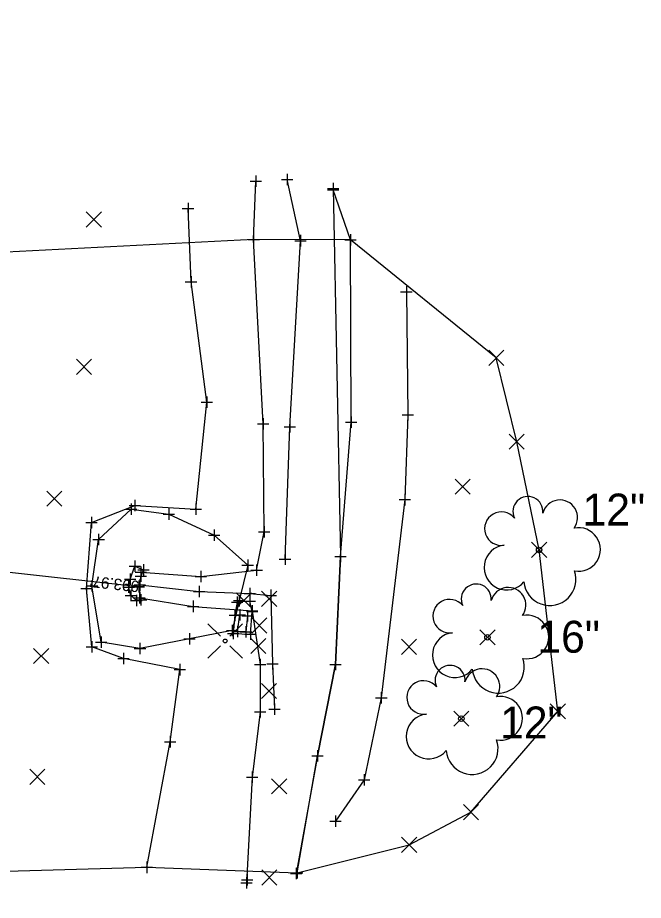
# Model space of a CAD drawing. Extents: x 160138 to 160780, y 488720 to 491073.
# Drawn here: x 160725.5 to 160780.4, y 489676.8 to 489754.3 of the extents above; entities that cross this region are included whole.
import ezdxf

# ---------------------------------------------------------------- set-up
doc = ezdxf.new("R2010")
doc.units = 0
for name, color, linetype in [('_CIVIL_CONSTRUCTION', 7, 'Continuous'), ('DR_X_Storm_Sewer', 7, 'Continuous'), ('RS_Raster1', 7, 'Continuous'), ('RW_X_CL_100_Bearings', 7, 'Continuous'), ('RW_X_CL_100_Cardinal_Points', 7, 'Continuous'), ('RW_X_CL_100_Curve_Data', 7, 'Continuous'), ('RW_X_CL_100_Stations', 7, 'Continuous'), ('SC_Scratch1', 7, 'Continuous'), ('SV_P_Control_Cells_Set', 7, 'Continuous'), ('SV_P_Mon_Cells_Set', 7, 'Continuous'), ('SV_X_Mon_Cells_Found', 7, 'Continuous'), ('SV_X_Random_Point', 7, 'Continuous'), ('SV_X_Terrain_Boundary', 7, 'Continuous'), ('VG_X_Text', 7, 'Continuous')]:
    doc.layers.add(name, color=color, linetype=linetype)

msp = doc.modelspace()

# ---------------------------------------------------------------- linework, layer by layer
at = {"layer": '_CIVIL_CONSTRUCTION'}
for p, q in [((160731.514, 489735.875), (160732.848, 489737.21)), ((160731.514, 489737.21), (160732.848, 489735.875)), ((160766.827, 489723.729), (160768.16, 489725.064)), ((160766.827, 489725.064), (160768.16, 489723.729)), ((160730.645, 489722.942), (160731.979, 489724.277)), ((160730.645, 489724.277), (160731.979, 489722.942)), ((160768.615, 489716.365), (160769.948, 489717.7)), ((160768.615, 489717.7), (160769.948, 489716.365)), ((160763.87, 489712.423), (160765.204, 489713.758)), ((160763.87, 489713.758), (160765.204, 489712.423)), ((160728.045, 489711.364), (160729.378, 489712.699)), ((160728.045, 489712.699), (160729.378, 489711.364)), ((160770.582, 489706.871), (160771.916, 489708.206)), ((160770.582, 489708.206), (160771.916, 489706.871)), ((160744.665, 489702.444), (160745.998, 489703.779)), ((160744.665, 489703.779), (160745.998, 489702.444)), ((160746.903, 489702.581), (160748.236, 489703.916)), ((160746.903, 489703.916), (160748.236, 489702.581)), ((160746.032, 489700.223), (160747.366, 489701.558)), ((160746.032, 489701.558), (160747.366, 489700.223)), ((160766.051, 489699.188), (160767.384, 489700.523)), ((160766.051, 489700.523), (160767.384, 489699.188)), ((160745.938, 489698.431), (160747.272, 489699.766)), ((160745.938, 489699.766), (160747.272, 489698.431)), ((160759.163, 489698.362), (160760.496, 489699.697)), ((160759.163, 489699.697), (160760.496, 489698.362)), ((160726.893, 489697.554), (160728.226, 489698.889)), ((160726.893, 489698.889), (160728.226, 489697.554)), ((160746.877, 489694.485), (160748.21, 489695.82)), ((160746.877, 489695.82), (160748.21, 489694.485)), ((160772.231, 489692.695), (160773.564, 489694.03)), ((160772.231, 489694.03), (160773.564, 489692.695)), ((160763.753, 489692.048), (160765.086, 489693.383)), ((160763.753, 489693.383), (160765.086, 489692.048)), ((160726.553, 489686.954), (160727.886, 489688.289)), ((160726.553, 489688.289), (160727.886, 489686.954)), ((160747.776, 489686.114), (160749.109, 489687.449)), ((160747.776, 489687.449), (160749.109, 489686.114)), ((160764.601, 489683.842), (160765.934, 489685.177)), ((160764.601, 489685.177), (160765.934, 489683.842)), ((160759.18, 489680.981), (160760.513, 489682.316)), ((160759.18, 489682.316), (160760.513, 489680.981)), ((160746.913, 489678.119), (160748.247, 489679.454)), ((160746.913, 489679.454), (160748.247, 489678.119))]:
    msp.add_line(p, q, dxfattribs=at)
at = {"layer": 'DR_X_Storm_Sewer'}
msp.add_line((160736.136, 489704.301), (160652.451, 489713.545), dxfattribs=at)
at = {"layer": 'RS_Raster1'}
for p, q in [((160736.136, 489704.801), (160736.136, 489703.801)), ((160735.636, 489704.301), (160736.636, 489704.301)), ((160736.136, 489704.301), (160736.136, 489704.301))]:
    msp.add_line(p, q, dxfattribs=at)
at = {"layer": 'RW_X_CL_100_Bearings'}
msp.add_lwpolyline([(160745.528, 489700.352), (160744.771, 489700.37), (160744.997, 489701.829), (160745.671, 489701.742)], close=True, dxfattribs=at)
at = {"layer": 'RW_X_CL_100_Cardinal_Points'}
msp.add_lwpolyline([(160753.172, 489739.247), (160753.811, 489706.959), (160753.388, 489697.468), (160751.807, 489689.466), (160749.924, 489679.123)], dxfattribs=at)
at = {"layer": 'RW_X_CL_100_Curve_Data'}
msp.add_lwpolyline([(160744.323, 489700.452), (160740.574, 489699.732), (160736.225, 489698.889), (160732.816, 489699.448), (160732.012, 489704.373), (160732.599, 489708.451), (160735.443, 489711.112), (160738.747, 489710.666), (160742.737, 489708.82), (160745.675, 489706.192), (160744.929, 489703.081)], close=True, dxfattribs=at)
at = {"layer": 'RW_X_CL_100_Stations'}
for points in [[(160736.118, 489704.337), (160736.312, 489703.141), (160735.911, 489703.083), (160735.435, 489703.534), (160735.231, 489704.253), (160735.368, 489704.977), (160735.784, 489706.102), (160736.535, 489705.78), (160736.3, 489705.244)], [(160745.923, 489700.131), (160746.061, 489702.117), (160745.874, 489703.037), (160744.764, 489702.95), (160744.557, 489701.793), (160744.397, 489700.186)]]:
    msp.add_lwpolyline(points, close=True, dxfattribs=at)
at = {"layer": 'SC_Scratch1'}
for centre in [(160771.249, 489707.538), (160766.718, 489699.856), (160764.419, 489692.716)]:
    msp.add_circle(centre, 0.24, dxfattribs=at)
for centre, radius, start, end in [((160770.265, 489710.906), 1.317, 354.0047, 205.97412), ((160773.075, 489710.367), 1.553, 323.82996, 165.0376), ((160767.94, 489709.402), 1.471, 39.06254, 279.54124), ((160774.709, 489707.574), 1.915, 259.14531, 101.45961), ((160768.396, 489705.989), 1.974, 96.17219, 320.57371), ((160772.195, 489704.933), 2.284, 184.94757, 19.45715), ((160765.734, 489703.223), 1.317, 354.0047, 205.97412), ((160768.544, 489702.685), 1.553, 323.82996, 165.0376), ((160763.408, 489701.72), 1.471, 39.06254, 279.54124), ((160770.178, 489699.892), 1.915, 259.14531, 101.45961), ((160763.864, 489698.307), 1.974, 96.17219, 320.57371), ((160767.664, 489697.251), 2.284, 184.94757, 19.45715), ((160763.436, 489696.083), 1.317, 354.0047, 205.97412), ((160766.245, 489695.545), 1.553, 323.82996, 165.0376), ((160761.11, 489694.58), 1.471, 39.06254, 279.54124), ((160767.88, 489692.752), 1.915, 259.14531, 101.45961), ((160761.566, 489691.167), 1.974, 96.17219, 320.57371), ((160765.366, 489690.11), 2.284, 184.94757, 19.45715)]:
    msp.add_arc(centre, radius, start, end, dxfattribs=at)
at = {"layer": 'SV_P_Control_Cells_Set'}
for points in [[(160736.304, 489705.57), (160741.571, 489705.195), (160746.464, 489705.762), (160747.123, 489709.112), (160747.042, 489718.613), (160746.199, 489734.784), (160746.384, 489739.897)], [(160750.025, 489679.19), (160751.807, 489689.466), (160753.388, 489697.468), (160753.811, 489706.959), (160754.767, 489718.753), (160754.691, 489734.763), (160753.182, 489739.146)], [(160736.83, 489679.671), (160738.864, 489690.7), (160739.733, 489697.024), (160734.784, 489698.012), (160732.007, 489699.033), (160731.536, 489704.152), (160731.967, 489709.933), (160735.764, 489711.422), (160741.126, 489711.11), (160742.084, 489720.498), (160740.703, 489731.065), (160740.439, 489737.511)], [(160759.598, 489730.175), (160759.723, 489719.384), (160759.475, 489711.945), (160757.404, 489694.557), (160755.902, 489687.362), (160753.382, 489683.72)], [(160736.191, 489703.32), (160740.901, 489702.58), (160746.06, 489702.174), (160746.77, 489697.47), (160746.777, 489693.319), (160746.067, 489687.577), (160745.58, 489678.302)]]:
    msp.add_lwpolyline(points, dxfattribs=at)
at = {"layer": 'SV_P_Mon_Cells_Set'}
for points in [[(160748.953, 489706.722), (160749.379, 489718.332), (160750.302, 489734.679), (160749.134, 489740.052)], [(160736.218, 489704.456), (160741.427, 489703.895), (160745.872, 489703.711), (160747.705, 489703.547), (160747.854, 489697.539), (160748.019, 489693.561)]]:
    msp.add_lwpolyline(points, dxfattribs=at)
at = {"layer": 'SV_X_Mon_Cells_Found'}
for p, q in [((160742.19, 489701.045), (160743.283, 489699.952)), ((160744.117, 489699.952), (160745.208, 489701.045)), ((160742.19, 489698.027), (160743.283, 489699.12)), ((160744.117, 489699.12), (160745.208, 489698.027))]:
    msp.add_line(p, q, dxfattribs=at)
msp.add_circle((160743.7, 489699.542), 0.17, dxfattribs=at)
at = {"layer": 'SV_X_Random_Point'}
for p, q in [((160746.384, 489740.397), (160746.384, 489739.397)), ((160749.134, 489740.552), (160749.134, 489739.552)), ((160745.884, 489739.897), (160746.884, 489739.897)), ((160746.384, 489739.897), (160746.384, 489739.897)), ((160748.634, 489740.052), (160749.634, 489740.052)), ((160749.134, 489740.052), (160749.134, 489740.052)), ((160753.172, 489739.747), (160753.172, 489738.747)), ((160753.182, 489739.646), (160753.182, 489738.646)), ((160752.672, 489739.247), (160753.672, 489739.247)), ((160752.682, 489739.146), (160753.682, 489739.146)), ((160753.172, 489739.247), (160753.172, 489739.247)), ((160753.182, 489739.146), (160753.182, 489739.146)), ((160740.439, 489738.011), (160740.439, 489737.011)), ((160739.939, 489737.511), (160740.939, 489737.511)), ((160740.439, 489737.511), (160740.439, 489737.511)), ((160745.699, 489734.784), (160746.699, 489734.784)), ((160746.199, 489735.284), (160746.199, 489734.284)), ((160746.199, 489734.784), (160746.199, 489734.784)), ((160750.302, 489735.179), (160750.302, 489734.179)), ((160754.191, 489734.763), (160755.191, 489734.763)), ((160754.691, 489735.263), (160754.691, 489734.263)), ((160754.691, 489734.763), (160754.691, 489734.763)), ((160749.802, 489734.679), (160750.802, 489734.679)), ((160750.302, 489734.679), (160750.302, 489734.679)), ((160740.203, 489731.065), (160741.203, 489731.065)), ((160740.703, 489731.565), (160740.703, 489730.565)), ((160740.703, 489731.065), (160740.703, 489731.065)), ((160759.098, 489730.175), (160760.098, 489730.175)), ((160759.598, 489730.675), (160759.598, 489729.675)), ((160759.598, 489730.175), (160759.598, 489730.175)), ((160742.084, 489720.998), (160742.084, 489719.998)), ((160741.584, 489720.498), (160742.584, 489720.498)), ((160742.084, 489720.498), (160742.084, 489720.498)), ((160754.767, 489719.253), (160754.767, 489718.253)), ((160759.223, 489719.384), (160760.223, 489719.384)), ((160759.723, 489719.884), (160759.723, 489718.884)), ((160759.723, 489719.384), (160759.723, 489719.384)), ((160746.542, 489718.613), (160747.542, 489718.613)), ((160747.042, 489719.113), (160747.042, 489718.113)), ((160747.042, 489718.613), (160747.042, 489718.613)), ((160749.379, 489718.832), (160749.379, 489717.832)), ((160754.267, 489718.753), (160755.267, 489718.753)), ((160754.767, 489718.753), (160754.767, 489718.753)), ((160748.879, 489718.332), (160749.879, 489718.332)), ((160749.379, 489718.332), (160749.379, 489718.332)), ((160759.475, 489712.445), (160759.475, 489711.445)), ((160735.443, 489711.612), (160735.443, 489710.612)), ((160735.764, 489711.922), (160735.764, 489710.922)), ((160741.126, 489711.61), (160741.126, 489710.61)), ((160758.975, 489711.945), (160759.975, 489711.945)), ((160759.475, 489711.945), (160759.475, 489711.945)), ((160734.943, 489711.112), (160735.943, 489711.112)), ((160735.264, 489711.422), (160736.264, 489711.422)), ((160735.443, 489711.112), (160735.443, 489711.112)), ((160735.764, 489711.422), (160735.764, 489711.422)), ((160738.747, 489711.166), (160738.747, 489710.166)), ((160740.626, 489711.11), (160741.626, 489711.11)), ((160741.126, 489711.11), (160741.126, 489711.11)), ((160731.467, 489709.933), (160732.467, 489709.933)), ((160731.967, 489710.433), (160731.967, 489709.433)), ((160731.967, 489709.933), (160731.967, 489709.933)), ((160738.247, 489710.666), (160739.247, 489710.666)), ((160738.747, 489710.666), (160738.747, 489710.666)), ((160742.737, 489709.32), (160742.737, 489708.32)), ((160747.123, 489709.612), (160747.123, 489708.612)), ((160732.099, 489708.451), (160733.099, 489708.451)), ((160732.599, 489708.951), (160732.599, 489707.951)), ((160732.599, 489708.451), (160732.599, 489708.451)), ((160742.237, 489708.82), (160743.237, 489708.82)), ((160742.737, 489708.82), (160742.737, 489708.82)), ((160746.623, 489709.112), (160747.623, 489709.112)), ((160747.123, 489709.112), (160747.123, 489709.112)), ((160748.953, 489707.222), (160748.953, 489706.222)), ((160753.311, 489706.959), (160754.311, 489706.959)), ((160753.311, 489706.959), (160754.311, 489706.959)), ((160753.811, 489707.459), (160753.811, 489706.459)), ((160753.811, 489707.459), (160753.811, 489706.459)), ((160753.811, 489706.959), (160753.811, 489706.959)), ((160753.811, 489706.959), (160753.811, 489706.959)), ((160735.284, 489706.102), (160736.284, 489706.102)), ((160735.784, 489706.602), (160735.784, 489705.602)), ((160735.784, 489706.102), (160735.784, 489706.102)), ((160736.304, 489706.07), (160736.304, 489705.07)), ((160736.535, 489706.28), (160736.535, 489705.28)), ((160745.175, 489706.192), (160746.175, 489706.192)), ((160745.675, 489706.692), (160745.675, 489705.692)), ((160745.675, 489706.192), (160745.675, 489706.192)), ((160746.464, 489706.262), (160746.464, 489705.262)), ((160748.453, 489706.722), (160749.453, 489706.722)), ((160748.953, 489706.722), (160748.953, 489706.722)), ((160735.368, 489705.477), (160735.368, 489704.477)), ((160735.804, 489705.57), (160736.804, 489705.57)), ((160736.035, 489705.78), (160737.035, 489705.78)), ((160736.3, 489705.744), (160736.3, 489704.744)), ((160736.304, 489705.57), (160736.304, 489705.57)), ((160736.535, 489705.78), (160736.535, 489705.78)), ((160741.571, 489705.695), (160741.571, 489704.695)), ((160745.964, 489705.762), (160746.964, 489705.762)), ((160746.464, 489705.762), (160746.464, 489705.762)), ((160731.536, 489704.652), (160731.536, 489703.652)), ((160732.012, 489704.873), (160732.012, 489703.873)), ((160734.868, 489704.977), (160735.868, 489704.977)), ((160735.231, 489704.753), (160735.231, 489703.753)), ((160735.368, 489704.977), (160735.368, 489704.977)), ((160735.8, 489705.244), (160736.8, 489705.244)), ((160736.118, 489704.837), (160736.118, 489703.837)), ((160736.218, 489704.956), (160736.218, 489703.956)), ((160736.3, 489705.244), (160736.3, 489705.244)), ((160741.071, 489705.195), (160742.071, 489705.195)), ((160741.571, 489705.195), (160741.571, 489705.195)), ((160731.036, 489704.152), (160732.036, 489704.152)), ((160731.512, 489704.373), (160732.512, 489704.373)), ((160731.536, 489704.152), (160731.536, 489704.152)), ((160732.012, 489704.373), (160732.012, 489704.373)), ((160734.731, 489704.253), (160735.731, 489704.253)), ((160735.231, 489704.253), (160735.231, 489704.253)), ((160735.435, 489704.034), (160735.435, 489703.034)), ((160735.618, 489704.337), (160736.618, 489704.337)), ((160735.718, 489704.456), (160736.718, 489704.456)), ((160736.118, 489704.337), (160736.118, 489704.337)), ((160736.191, 489703.82), (160736.191, 489702.82)), ((160736.218, 489704.456), (160736.218, 489704.456)), ((160740.927, 489703.895), (160741.927, 489703.895)), ((160741.427, 489704.395), (160741.427, 489703.395)), ((160741.427, 489703.895), (160741.427, 489703.895)), ((160745.372, 489703.711), (160746.372, 489703.711)), ((160745.872, 489704.211), (160745.872, 489703.211)), ((160745.872, 489703.711), (160745.872, 489703.711)), ((160747.705, 489704.047), (160747.705, 489703.047)), ((160734.935, 489703.534), (160735.935, 489703.534)), ((160735.411, 489703.083), (160736.411, 489703.083)), ((160735.435, 489703.534), (160735.435, 489703.534)), ((160735.691, 489703.32), (160736.691, 489703.32)), ((160735.812, 489703.141), (160736.812, 489703.141)), ((160735.911, 489703.583), (160735.911, 489702.583)), ((160735.911, 489703.083), (160735.911, 489703.083)), ((160736.191, 489703.32), (160736.191, 489703.32)), ((160736.312, 489703.641), (160736.312, 489702.641)), ((160736.312, 489703.141), (160736.312, 489703.141)), ((160740.901, 489703.08), (160740.901, 489702.08)), ((160744.264, 489702.95), (160745.264, 489702.95)), ((160744.429, 489703.081), (160745.429, 489703.081)), ((160744.764, 489703.45), (160744.764, 489702.45)), ((160744.764, 489702.95), (160744.764, 489702.95)), ((160744.929, 489703.581), (160744.929, 489702.581)), ((160744.929, 489703.081), (160744.929, 489703.081)), ((160745.374, 489703.037), (160746.374, 489703.037)), ((160745.874, 489703.537), (160745.874, 489702.537)), ((160745.874, 489703.037), (160745.874, 489703.037)), ((160747.205, 489703.547), (160748.205, 489703.547)), ((160747.705, 489703.547), (160747.705, 489703.547)), ((160740.401, 489702.58), (160741.401, 489702.58)), ((160740.901, 489702.58), (160740.901, 489702.58)), ((160744.557, 489702.293), (160744.557, 489701.293)), ((160744.997, 489702.329), (160744.997, 489701.329)), ((160745.56, 489702.174), (160746.56, 489702.174)), ((160745.671, 489702.242), (160745.671, 489701.242)), ((160746.06, 489702.674), (160746.06, 489701.674)), ((160746.06, 489702.174), (160746.06, 489702.174)), ((160746.061, 489702.617), (160746.061, 489701.617)), ((160744.057, 489701.793), (160745.057, 489701.793)), ((160744.497, 489701.829), (160745.497, 489701.829)), ((160744.557, 489701.793), (160744.557, 489701.793)), ((160744.997, 489701.829), (160744.997, 489701.829)), ((160745.171, 489701.742), (160746.171, 489701.742)), ((160745.561, 489702.117), (160746.561, 489702.117)), ((160745.671, 489701.742), (160745.671, 489701.742)), ((160746.061, 489702.117), (160746.061, 489702.117)), ((160744.323, 489700.952), (160744.323, 489699.952)), ((160744.397, 489700.686), (160744.397, 489699.686)), ((160744.771, 489700.87), (160744.771, 489699.87)), ((160745.528, 489700.852), (160745.528, 489699.852)), ((160745.923, 489700.631), (160745.923, 489699.631)), ((160732.816, 489699.948), (160732.816, 489698.948)), ((160740.574, 489700.232), (160740.574, 489699.232)), ((160743.823, 489700.452), (160744.823, 489700.452)), ((160743.897, 489700.186), (160744.897, 489700.186)), ((160744.271, 489700.37), (160745.271, 489700.37)), ((160744.323, 489700.452), (160744.323, 489700.452)), ((160744.397, 489700.186), (160744.397, 489700.186)), ((160744.771, 489700.37), (160744.771, 489700.37)), ((160745.028, 489700.352), (160746.028, 489700.352)), ((160745.423, 489700.131), (160746.423, 489700.131)), ((160745.528, 489700.352), (160745.528, 489700.352)), ((160745.923, 489700.131), (160745.923, 489700.131)), ((160732.007, 489699.533), (160732.007, 489698.533)), ((160732.316, 489699.448), (160733.316, 489699.448)), ((160732.816, 489699.448), (160732.816, 489699.448)), ((160736.225, 489699.389), (160736.225, 489698.389)), ((160740.074, 489699.732), (160741.074, 489699.732)), ((160740.574, 489699.732), (160740.574, 489699.732)), ((160731.507, 489699.033), (160732.507, 489699.033)), ((160732.007, 489699.033), (160732.007, 489699.033)), ((160734.784, 489698.512), (160734.784, 489697.512)), ((160735.725, 489698.889), (160736.725, 489698.889)), ((160736.225, 489698.889), (160736.225, 489698.889)), ((160734.284, 489698.012), (160735.284, 489698.012)), ((160734.784, 489698.012), (160734.784, 489698.012)), ((160739.733, 489697.524), (160739.733, 489696.524)), ((160746.77, 489697.97), (160746.77, 489696.97)), ((160747.354, 489697.539), (160748.354, 489697.539)), ((160747.854, 489698.039), (160747.854, 489697.039)), ((160747.854, 489697.539), (160747.854, 489697.539)), ((160753.388, 489697.968), (160753.388, 489696.968)), ((160753.388, 489697.968), (160753.388, 489696.968)), ((160739.233, 489697.024), (160740.233, 489697.024)), ((160739.733, 489697.024), (160739.733, 489697.024)), ((160746.27, 489697.47), (160747.27, 489697.47)), ((160746.77, 489697.47), (160746.77, 489697.47)), ((160752.888, 489697.468), (160753.888, 489697.468)), ((160752.888, 489697.468), (160753.888, 489697.468)), ((160753.388, 489697.468), (160753.388, 489697.468)), ((160753.388, 489697.468), (160753.388, 489697.468)), ((160756.904, 489694.557), (160757.904, 489694.557)), ((160757.404, 489695.057), (160757.404, 489694.057)), ((160757.404, 489694.557), (160757.404, 489694.557)), ((160746.777, 489693.819), (160746.777, 489692.819)), ((160748.019, 489694.061), (160748.019, 489693.061)), ((160746.277, 489693.319), (160747.277, 489693.319)), ((160746.777, 489693.319), (160746.777, 489693.319)), ((160747.519, 489693.561), (160748.519, 489693.561)), ((160748.019, 489693.561), (160748.019, 489693.561)), ((160738.364, 489690.7), (160739.364, 489690.7)), ((160738.864, 489691.2), (160738.864, 489690.2)), ((160738.864, 489690.7), (160738.864, 489690.7)), ((160751.807, 489689.966), (160751.807, 489688.966)), ((160751.807, 489689.966), (160751.807, 489688.966)), ((160751.307, 489689.466), (160752.307, 489689.466)), ((160751.307, 489689.466), (160752.307, 489689.466)), ((160751.807, 489689.466), (160751.807, 489689.466)), ((160751.807, 489689.466), (160751.807, 489689.466)), ((160745.567, 489687.577), (160746.567, 489687.577)), ((160746.067, 489688.077), (160746.067, 489687.077)), ((160746.067, 489687.577), (160746.067, 489687.577)), ((160755.902, 489687.862), (160755.902, 489686.862)), ((160755.402, 489687.362), (160756.402, 489687.362)), ((160755.902, 489687.362), (160755.902, 489687.362)), ((160752.882, 489683.72), (160753.882, 489683.72)), ((160753.382, 489684.22), (160753.382, 489683.22)), ((160753.382, 489683.72), (160753.382, 489683.72)), ((160736.83, 489680.171), (160736.83, 489679.171)), ((160750.025, 489679.69), (160750.025, 489678.69)), ((160736.33, 489679.671), (160737.33, 489679.671)), ((160736.83, 489679.671), (160736.83, 489679.671)), ((160745.623, 489679.072), (160745.623, 489678.072)), ((160749.424, 489679.123), (160750.424, 489679.123)), ((160749.525, 489679.19), (160750.525, 489679.19)), ((160749.924, 489679.623), (160749.924, 489678.623)), ((160749.924, 489679.123), (160749.924, 489679.123)), ((160750.025, 489679.19), (160750.025, 489679.19)), ((160745.08, 489678.302), (160746.08, 489678.302)), ((160745.123, 489678.572), (160746.123, 489678.572)), ((160745.58, 489678.802), (160745.58, 489677.802)), ((160745.58, 489678.302), (160745.58, 489678.302)), ((160745.623, 489678.572), (160745.623, 489678.572))]:
    msp.add_line(p, q, dxfattribs=at)
at = {"layer": 'SV_X_Terrain_Boundary'}
msp.add_lwpolyline([(160514.912, 489637.894), (160547.865, 489638.238), (160565.434, 489639.08), (160616.189, 489674.183), (160652.272, 489681.356), (160684.014, 489678.351), (160707.031, 489678.823), (160736.83, 489679.671), (160750.025, 489679.19), (160759.846, 489681.649), (160765.268, 489684.51), (160772.898, 489693.362), (160771.249, 489707.538), (160769.281, 489717.032), (160767.493, 489724.397), (160754.691, 489734.763), (160746.199, 489734.784), (160717.641, 489733.306), (160642.598, 489754.256), (160573.958, 489735.815), (160560.406, 489729.318), (160491.054, 489700.611)], dxfattribs=at)

# ---------------------------------------------------------------- texts
at = {"layer": 'SC_Scratch1'}
msp.add_text("993.97'", height=1, rotation=173.69651, dxfattribs=at).set_placement((160736.191, 489704.798))
at = {"layer": 'VG_X_Text'}
for s, p in [('12"', (160775.061, 489709.676)), ('16"', (160771.095, 489698.511)), ('12"', (160767.825, 489690.985))]:
    msp.add_text(s, height=2.8, dxfattribs=at).set_placement(p)

doc.saveas('drawing.dxf')
